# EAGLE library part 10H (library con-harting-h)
CONNECTOR
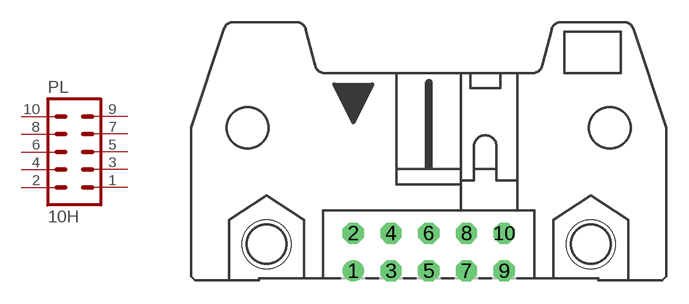
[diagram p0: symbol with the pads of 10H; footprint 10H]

Designator prefix PL

## 10H (OC_FARNELL: unknown; OC_NEWARK: unknown)  [10H]
1  1  pas
2  2  pas
3  3  pas
4  4  pas
5  5  pas
6  6  pas
7  7  pas
8  8  pas
9  9  pas
10  10  pas

## Footprint 10H (pad centres in mm)
CONNECTOR
drill 0.914 round: 1 -5.08,-1.27
drill 0.914 octagon: 2 -5.08,1.27; 3 -2.54,-1.27; 4 -2.54,1.27; 5 0,-1.27; 6 0,1.27; 7 2.54,-1.27; 8 2.54,1.27; 9 5.08,-1.27; 10 5.08,1.27
hole 3.302 at -10.922,0.533
hole 3.302 at 10.922,0.533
